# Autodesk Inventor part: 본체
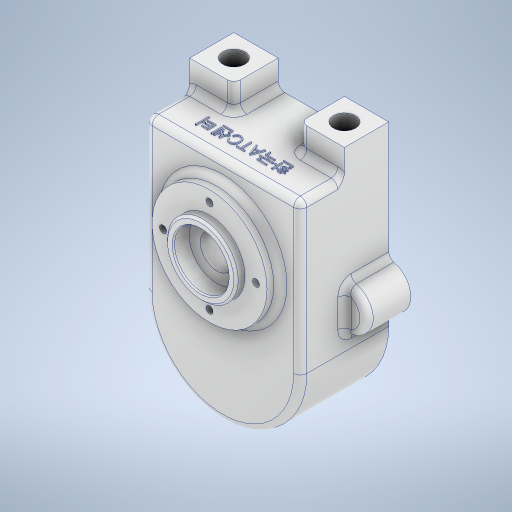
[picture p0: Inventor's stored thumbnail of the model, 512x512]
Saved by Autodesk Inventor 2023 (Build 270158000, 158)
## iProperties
Created: 2024-03
Part Number: 본체
Material: 알루미늄 6061
Document SubType Name: Modeling
Designer: asung
Density: 2.7 g/cm^3
Appearance: 알루미늄 - 평지
Author: asung
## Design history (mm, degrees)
sketch "스케치1"
  geometry: L1 (-35, -34)-(35, -34); L2 (35, -34)-(35, 34); L3 (35, 34)-(-35, 34); L4 (-35, 34)-(-35, -34); L5 (-35, -34)-(35, 34); L6 (35, -34)-(-35, 34); 3 further points
  constraints: 12 end point, 3 midpoint, 2 parallel, 1 horizontal, 1 perpendicular, 3 other
  dimensions: "d0" = 70 distance of L3.end L2.end; "d1" = 68 distance of L2.end L1.end
extrude "돌출1" new body sketch "스케치1" distance "d2" = 40; taper "d3" = 0 deg
sketch "스케치2"
  geometry: L1 (35, 34)-(35, -34) reference; L2 (-35, 34)-(35, 34) reference; L3 (-35, -34)-(-35, 34) reference; L4 (35, 34)-(15, 34); L5 (15, 34)-(15, 46); L6 (15, 46)-(35, 46); L7 (35, 46)-(35, 34); L8 (-35, 34)-(-15, 34); L9 (-15, 34)-(-15, 46); L10 (-15, 46)-(-35, 46); L11 (-35, 46)-(-35, 34); A1 r 35 centre (0, -34) between (-35, -34) and (35, -34) reference; 3 further points
  constraints: 16 end point, 4 parallel, 2 horizontal, 2 perpendicular
  dimensions: "d8" = 20 distance of L5.end L6.end; "d9" = 12 distance of L4.end L5.end; "d10" = 20 distance of L10.end L9.end; "d11" = 12 distance of L9.end L8.end
extrude "돌출2" join sketch "스케치2" distance "d12" = 20; taper "d13" = 0 deg
sketch "스케치3"
  geometry: L1 (-35, 34)-(-35, -34) reference; L2 (35, -34)-(35, 34) reference; L3 (35, 34)-(-35, 34) reference; C1 r 26 at (0, -1); A1 r 35 centre (0, -34) between (-35, -34) and (35, -34) reference; 1 further point
  constraints: 1 centre point, 1 vertical alignment
  dimensions: "d14" = 52 diameter of C1; "d15" = 33 vertical distance of L2.start C1.centre
extrude "돌출3" join sketch "스케치3" distance "d16" = 6; taper "d17" = 0 deg
sketch "스케치4"
  geometry: C1 r 26 at (0, 0) reference; C2 r 16 at (0, 0); 1 further point
  constraints: 1 centre point, 1 coincident
  dimensions: "d18" = 32 diameter of C2
extrude "돌출4" join sketch "스케치4" distance "d19" = 4; taper "d20" = 0 deg
fillet "모깎기1" dims "d21" = 3
fillet "모깎기2" dims "d22" = 3
fillet "모깎기3" dims "d23" = 3
sketch "스케치5"
  geometry: L1 (35, 46)-(35, -34) reference; L2 (35, 46)-(15, 46) reference; L3 (15, 46)-(15, 37) reference; L4 (-12, 34)-(12, 34) reference; L5 (-15, 37)-(-15, 46) reference; L6 (-15, 46)-(-35, 46) reference; L7 (-35, -34)-(-35, 46) reference; L8 (-14, -27.5)-(14, -27.5); L9 (14, -27.5)-(14, -7.5); L10 (14, -7.5)-(-14, -7.5); L11 (-14, -7.5)-(-14, -27.5); L12 (-14, -27.5)-(14, -7.5); L13 (14, -27.5)-(-14, -7.5); C1 r 18 at (0, -34); C2 r 18 at (0, -1); A1 r 3 centre (12, 37) between (12, 34) and (15, 37) reference; A2 r 3 centre (-12, 37) between (-15, 37) and (-12, 34) reference; A3 r 35 centre (0, -34) between (-35, -34) and (35, -34) reference; 6 further points
  constraints: 12 end point, 2 centre point, 2 midpoint, 2 parallel, 2 vertical alignment, 1 coincident, 1 horizontal, 1 perpendicular
  dimensions: "d24" = 36 diameter of C1; "d25" = 36 diameter of C2; "d26" = 33 distance of A3.centre C2.centre; "d27" = 28 distance of L10.end L9.end; "d28" = 20 distance of L9.end L8.end; "d29" = 63.5 distance from line of point (0, -17.5) L2
extrude "돌출5" cut sketch "스케치5" distance "d30" = 20; taper "d31" = 0 deg
sketch "스케치6"
  geometry: A1 r 18 centre (0, -34) between (-14, -22.686) and (14, -22.686) reference; 2 further points
  constraints: 1 coincident
hole "구멍1" sketch "스케치6" at (0, -34) diameter "d32" = 20; stored, may be unused: countersink angle "d36" = 90 deg, drill point angle "d38" = 0 deg; dims "d33" = 8, "d34" = 4, "d35" = 2, "d37" = 10
sketch "스케치7"
  geometry: A1 r 18 centre (0, -1) between (14, -12.314) and (-14, -12.314) reference; 2 further points
  constraints: 1 coincident
hole "구멍2" sketch "스케치7" at (0, -1) diameter "d39" = 15; stored, may be unused: countersink angle "d43" = 90 deg, drill point angle "d45" = 0 deg; dims "d40" = 6, "d41" = 20, "d42" = 10, "d44" = 50
sketch "스케치8"
  geometry: C1 r 16 at (0, 0) reference; 2 further points
  constraints: 1 coincident
hole "구멍3" sketch "스케치8" at (0, 0) diameter "d46" = 25; stored, may be unused: countersink angle "d50" = 90 deg, drill point angle "d52" = 0 deg; dims "d47" = 6, "d48" = 20, "d49" = 10, "d51" = 7.3
chamfer "모따기1" distance "d53" = 1; stored, may be unused: second distance "d54" = 2, angle "d55" = 45 deg
chamfer "모따기2" distance "d56" = 0.7; stored, may be unused: second distance "d57" = 2, angle "d58" = 30 deg
sketch "스케치9" dims "d59" = 42
  geometry: C1 r 12.5 at (0, 0) reference; C2 r 26 at (0, 0) reference; C3 r 16 at (0, 0) reference; 3 further points
  constraints: 1 coincident, 1 vertical alignment, 2 other
hole "구멍4" sketch "스케치9" at (0, 21) diameter "d60" = 3.242; stored, may be unused: countersink angle "d64" = 90 deg, drill point angle "d66" = 118 deg; dims "d61" = 8, "d62" = 4, "d63" = 2, "d65" = 10
sketch "스케치10"
  geometry: L1 (-14, -22.686)-(-14, -12.314) reference; L2 (14, -12.314)-(14, -22.686) reference; L3 (35, 46)-(35, -34) reference; L4 (35, 46)-(15, 46) reference; L5 (15, 46)-(15, 37) reference; L6 (-12, 34)-(12, 34) reference; L7 (-15, 37)-(-15, 46) reference; L8 (-15, 46)-(-35, 46) reference; L9 (-35, -34)-(-35, 46) reference; C1 r 10 at (35, -17.5); C2 r 10 at (-35, -17.5); A1 r 18 centre (0, -1) between (14, -12.314) and (-14, -12.314) reference; A2 r 18 centre (0, -34) between (-14, -22.686) and (14, -22.686) reference; A3 r 3 centre (12, 37) between (12, 34) and (15, 37) reference; A4 r 3 centre (-12, 37) between (-15, 37) and (-12, 34) reference; A5 r 35 centre (0, -34) between (-35, -34) and (35, -34) reference; 5 further points
  constraints: 2 centre point, 2 point on line
  dimensions: "d70" = 10 radius of C1; "d71" = 63.5 distance from line of L4 C1.centre; "d72" = 10 radius of C2; "d73" = 63.5 distance from line of C2.centre L8
extrude "돌출6" join sketch "스케치10" distance "d74" = 20; taper "d75" = 0 deg
sketch "스케치11"
  geometry: A1 r 10 centre (35, -17.5) between (35, -27.5) and (35, -7.5) reference; A2 r 10 centre (-35, -17.5) between (-35, -7.5) and (-35, -27.5) reference; 3 further points
  constraints: 2 coincident
hole "구멍5" sketch "스케치11" at (35, -17.5), (-35, -17.5) diameter "d76" = 4.134; stored, may be unused: countersink angle "d80" = 90 deg, drill point angle "d82" = 118 deg; dims "d77" = 10, "d78" = 4, "d79" = 2, "d81" = 12
sketch "스케치12"
  geometry: A1 r 18 centre (0, -34) between (-14, -22.686) and (14, -22.686) reference; 2 further points
  constraints: 1 coincident
hole "구멍6" sketch "스케치12" at (0, -34) diameter "d83" = 14; stored, may be unused: countersink angle "d87" = 90 deg, drill point angle "d89" = 120 deg; dims "d84" = 6, "d85" = 4, "d86" = 2, "d88" = 10
fillet "모깎기4" dims "d90" = 3
fillet "모깎기5" dims "d91" = 3
chamfer "모따기3" distance "d92" = 1; stored, may be unused: second distance "d93" = 2, angle "d94" = 30 deg
sketch "스케치13"
  geometry: L1 (-14, -22.686)-(-14, -12.314) reference; L2 (14, -12.314)-(14, -22.686) reference; L3 (35, 46)-(35, -4.851) reference; L4 (35, 46)-(15, 46) reference; L5 (15, 46)-(15, 37) reference; L6 (-12, 34)-(12, 34) reference; L7 (-15, 37)-(-15, 46) reference; L8 (-15, 46)-(-35, 46) reference; L9 (-35, -4.851)-(-35, 46) reference; L10 (-35, -34)-(-35, -30.149) reference; L11 (35, -30.149)-(35, -34) reference; L12 (0, -34)-(0, -60); C1 r 2.067 at (35, -17.5) reference; C2 r 2.067 at (-35, -17.5) reference; A1 r 18 centre (0, -1) between (14, -12.314) and (-14, -12.314) reference; A2 r 18 centre (0, -34) between (-14, -22.686) and (14, -22.686) reference; A3 r 3 centre (12, 37) between (12, 34) and (15, 37) reference; A4 r 3 centre (-12, 37) between (-15, 37) and (-12, 34) reference; A5 r 3 centre (-38, -4.851) between (-37.308, -7.77) and (-35, -4.851) reference; A6 r 10 centre (-35, -17.5) between (-37.308, -7.77) and (-37.308, -27.23) reference; A7 r 3 centre (-38, -30.149) between (-35, -30.149) and (-37.308, -27.23) reference; A8 r 35 centre (0, -34) between (-35, -34) and (35, -34) reference; A9 r 3 centre (38, -30.149) between (37.308, -27.23) and (35, -30.149) reference; A10 r 10 centre (35, -17.5) between (37.308, -27.23) and (37.308, -7.77) reference; A11 r 3 centre (38, -4.851) between (35, -4.851) and (37.308, -7.77) reference; 3 further points
  constraints: 2 end point, 1 coincident, 1 vertical
  dimensions: "d95" = 26 distance of L12.start L12.end; "d136" = 26 distance of A1.centre point (0, 25)
hole "구멍7" sketch "스케치13" at (0, -60), (0, 25) diameter "d97" = 4.134; stored, may be unused: countersink angle "d101" = 90 deg, drill point angle "d103" = 118 deg; dims "d98" = 10, "d99" = 4, "d100" = 2, "d102" = 12
sketch "스케치14"
  geometry: L1 (-25.308, 0)-(-33, 0) reference; L2 (24, 0)-(0, 0) reference; 3 further points
  constraints: 1 midpoint, 1 vertical alignment, 1 other
  dimensions: "d104" = 30 distance from line of L1 point (12, -30)
feature "엠보싱1" sketch "스케치14" dims "d10" = 20, "d11" = 12, "d105" = 0.5, "d106" = 0
sketch "스케치15"
  geometry: L1 (30, 0)-(22.308, 0) reference; L2 (-52.308, 0)-(-60, 0) reference; L3 (20, 0)-(20, -20) reference; 3 further points
  dimensions: "d107" = 50 distance of point (-40, -10) point (10, -10); "d108" = 10 distance from line of L1 point (10, -10); "d109" = 10 distance from line of L2 point (-40, -10); "d110" = 10 distance from line of point (10, -10) L3
hole "구멍8" sketch "스케치15" at (10, -10), (-40, -10) diameter "d111" = 10; stored, may be unused: countersink angle "d115" = 90 deg, drill point angle "d117" = 0 deg; dims "d112" = 10, "d113" = 4, "d114" = 2, "d116" = 16
feature "스레드1" dims "d118" = 12, "d119" = 4
node "작업 평면1"
feature "스레드2" dims "d121" = 12, "d122" = 0
sketch "스케치16"
  geometry: L1 (-35, -4.851)-(-35, 46) reference; L2 (-35, 46)-(-30, 46) reference; L3 (-30, 46)-(-30, 30) reference; L4 (-30, 30)-(-20, 30) reference; L5 (-20, 30)-(-20, 46) reference; L6 (-20, 46)-(-15, 46) reference; L7 (-15, 46)-(-15, 37) reference; L8 (-12, 34)-(12, 34) reference; L9 (15, 37)-(15, 46) reference; L10 (15, 46)-(20, 46) reference; L11 (20, 46)-(20, 30) reference; L12 (20, 30)-(30, 30) reference; L13 (30, 30)-(30, 46) reference; L14 (30, 46)-(35, 46) reference; L15 (35, 46)-(35, -4.851) reference; L16 (35, -30.149)-(35, -34) reference; L17 (-35, -34)-(-35, -30.149) reference; L18 (-14, -12.314)-(-14, -22.686) reference; L19 (14, -22.686)-(14, -12.314) reference; L20 (-25, 30)-(-25, -17.5); L21 (-22, 30)-(-22, -17.5); L22 (-22, -17.5)-(-25, -17.5); L23 (0, 25)-(0, 1); L24 (25, 30)-(25, -17.5); L25 (22, 30)-(22, -17.5); L26 (22, -17.5)-(25, -17.5); C1 r 2.067 at (0, -60) reference; C2 r 2.067 at (0, 25) reference; C3 r 2.067 at (35, -17.5) reference; C4 r 2.067 at (-35, -17.5) reference; A1 r 3 centre (-38, -4.851) between (-37.308, -7.77) and (-35, -4.851) reference; A2 r 3 centre (-12, 37) between (-15, 37) and (-12, 34) reference; A3 r 3 centre (12, 37) between (12, 34) and (15, 37) reference; A4 r 3 centre (38, -4.851) between (35, -4.851) and (37.308, -7.77) reference; A5 r 10 centre (35, -17.5) between (37.308, -27.23) and (37.308, -7.77) reference; A6 r 3 centre (38, -30.149) between (37.308, -27.23) and (35, -30.149) reference; A7 r 35 centre (0, -34) between (-35, -34) and (35, -34) reference; A8 r 3 centre (-38, -30.149) between (-35, -30.149) and (-37.308, -27.23) reference; A9 r 10 centre (-35, -17.5) between (-37.308, -7.77) and (-37.308, -27.23) reference; A10 r 18 centre (0, -34) between (-14, -22.686) and (14, -22.686) reference; A11 r 18 centre (0, -1) between (14, -12.314) and (-14, -12.314) reference; 4 further points
  constraints: 14 end point, 4 symmetric about line, 2 vertical, 1 horizontal, 1 midpoint, 1 parallel
  dimensions: "d123" = 47.5 distance of L20.start L20.end; "d125" = 3 distance between parallel lines of L20 L21
  node "절단 모서리 투영2"
revolve "회전1" stored, may be unused: angle "d126" = 90 deg
revolve "회전2" stored, may be unused: angle "d127" = 90 deg
chamfer "모따기4" distance "d128" = 1; stored, may be unused: second distance "d129" = 2, angle "d130" = 30 deg
node "작업 평면2"
sketch "스케치17"
  geometry: L1 (-35, -4.851)-(-35, 46) reference; L2 (-35, 46)-(-30, 46) reference; L3 (-30, 46)-(-30, 31) reference; L4 (-30, 31)-(-29, 30) reference; L5 (-29, 30)-(-28, 30) reference; L6 (-28, 30)-(-28, -17.5) reference; L7 (-28, -17.5)-(-22, -17.5) reference; L8 (-22, -17.5)-(-22, 30) reference; L9 (-22, 30)-(-21, 30) reference; L10 (-21, 30)-(-20, 31) reference; L11 (-20, 31)-(-20, 46) reference; L12 (-20, 46)-(-15, 46) reference; L13 (-15, 46)-(-15, 37) reference; L14 (-12, 34)-(12, 34) reference; L15 (15, 37)-(15, 46) reference; L16 (15, 46)-(20, 46) reference; L17 (20, 46)-(20, 31) reference; L18 (20, 31)-(21, 30) reference; L19 (21, 30)-(22, 30) reference; L20 (22, 30)-(22, -17.5) reference; L21 (22, -17.5)-(28, -17.5) reference; L22 (28, -17.5)-(28, 30) reference; L23 (28, 30)-(29, 30) reference; L24 (29, 30)-(30, 31) reference; L25 (30, 31)-(30, 46) reference; L26 (30, 46)-(35, 46) reference; L27 (35, 46)-(35, -4.851) reference; L28 (35, -30.149)-(35, -34) reference; L29 (-35, -34)-(-35, -30.149) reference; L30 (-14, -12.314)-(-14, -22.686) reference; L31 (14, -22.686)-(14, -12.314) reference; L32 (-22, -17.5)-(22, -17.5); L33 (-17, -17.5)-(-17, -14.5); L34 (-17, -14.5)-(17, -14.5); L35 (17, -14.5)-(17, -17.5); C1 r 2.067 at (0, -60) reference; C2 r 2.067 at (0, 25) reference; C3 r 2.067 at (35, -17.5) reference; C4 r 2.067 at (-35, -17.5) reference; A1 r 3 centre (-38, -4.851) between (-37.308, -7.77) and (-35, -4.851) reference; A2 r 3 centre (-12, 37) between (-15, 37) and (-12, 34) reference; A3 r 3 centre (12, 37) between (12, 34) and (15, 37) reference; A4 r 3 centre (38, -4.851) between (35, -4.851) and (37.308, -7.77) reference; A5 r 10 centre (35, -17.5) between (37.308, -27.23) and (37.308, -7.77) reference; A6 r 3 centre (38, -30.149) between (37.308, -27.23) and (35, -30.149) reference; A7 r 35 centre (0, -34) between (-35, -34) and (35, -34) reference; A8 r 3 centre (-38, -30.149) between (-35, -30.149) and (-37.308, -27.23) reference; A9 r 10 centre (-35, -17.5) between (-37.308, -7.77) and (-37.308, -27.23) reference; A10 r 18 centre (0, -34) between (-14, -22.686) and (14, -22.686) reference; A11 r 18 centre (0, -1) between (14, -12.314) and (-14, -12.314) reference; 3 further points
  constraints: 8 end point, 2 perpendicular, 2 point on line, 1 collinear, 1 vertical
  dimensions: "d132" = 6 diameter of L34 L32; "d133" = 34 distance between parallel lines of L35 L33; "d134" = 3 distance between parallel lines of L31 L35
revolve "회전3" sketch "스케치17" stored, may be unused: angle "d135" = 360 deg
feature "Ź耀Ż耀Ž耀ſ耀Ɓ耀ƃ耀ƅ耀Ƈ耀" dims "d0" = 70, "d1" = 68, "d2" = 40, "d3" = 0, "d8" = 20, "d9" = 12, "d10" = 20, "d11" = 12, "d12" = 20, "d13" = 0, "d14" = 52, "d15" = 33, "d16" = 6, "d17" = 0, "d18" = 32, "d19" = 4, "d20" = 0, "d21" = 3, "d22" = 3, "d23" = 3, "d24" = 36, "d25" = 36, "d26" = 33, "d27" = 28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
node "솔리드1"
pattern_circular "원형 패턴1" dims angle "d68" = 360 deg
node "투영된 루프1"
node "투영된 루프2"
node "투영된 루프3"
node "투영된 루프4"
node "투영된 루프5"
node "투영된 루프6"
feature "A9D066F2-1C7D-4E18-AEED-F7BC21143FA4" dims "d118" = 12, "d119" = 4
node "절단 모서리 투영1"
node "절단 모서리 투영3"
